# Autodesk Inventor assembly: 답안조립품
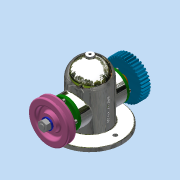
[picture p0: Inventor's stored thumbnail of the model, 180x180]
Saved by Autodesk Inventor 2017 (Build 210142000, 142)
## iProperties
Created: 2019-11
Part Number: 답안조립품
Document SubType Name: Assembly
Designer: 1-17-lg
Author: 1-17-lg
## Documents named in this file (14)
- C:\Users\1-17-lg\Desktop\491104V1011\답안조립품.iam.iam
- C:\Users\1-17-lg\Desktop\491104V1011\본체.ipt
- C:\Users\1-17-lg\Desktop\491104V1011\V-벨트풀리.ipt
- V-벨트풀리.ipt
- C:\Users\1-17-lg\Desktop\491104V1011\너트 M12x1.25.ipt
- C:\Users\1-17-lg\Desktop\491104V1011\베어링 6203.ipt
- C:\Users\1-17-lg\Desktop\491104V1011\볼트 M4.ipt
- C:\Users\1-17-lg\Desktop\491104V1011\부시.ipt
- C:\Users\1-17-lg\Desktop\491104V1011\스퍼기어.ipt
- C:\Users\1-17-lg\Desktop\491104V1011\오일 실 26 38 8.ipt
- C:\Users\1-17-lg\Desktop\491104V1011\와셔 12x24.ipt
- C:\Users\1-17-lg\Desktop\491104V1011\축.ipt
- C:\Users\1-17-lg\Desktop\491104V1011\커버.ipt
- C:\Users\1-17-lg\Desktop\491104V1011\키 5x5x12.ipt
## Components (1 placed, 1 different names)
1. V-벨트풀리:1 — Mate:27, Mate:28, Mate:29, Mate:35
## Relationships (4: Mate 4)
- Mate:27: V-벨트풀리:1
- Mate:28: V-벨트풀리:1
- Mate:29: V-벨트풀리:1
- Mate:35: V-벨트풀리:1
